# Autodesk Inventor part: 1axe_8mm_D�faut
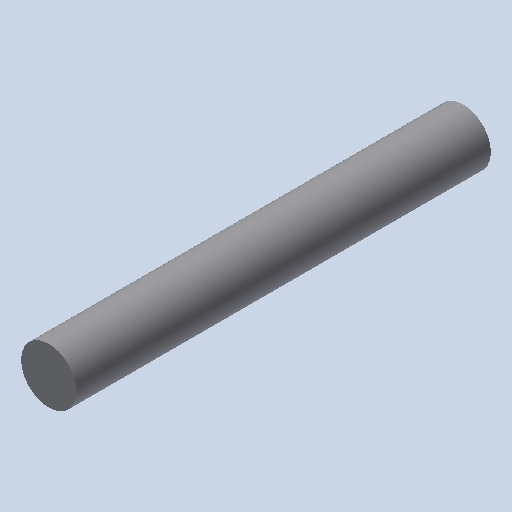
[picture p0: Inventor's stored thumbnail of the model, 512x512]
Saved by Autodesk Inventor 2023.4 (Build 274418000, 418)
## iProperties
Created: 2011-01
Part Number: 1axe_8mm_D�faut
Document SubType Name: Modeling
Designer: eric
Density: 1 g/cm^3
Mass: 3.01593 g
Surface Area: 16.085 cm^2
Volume: 3.01593 cm^3
Material: Générique
Appearance: Par défaut
Author: eric
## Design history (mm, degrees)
feature "Base1"
node "Corps solides"
node "Corps surfaciques"
node "Solide1"
